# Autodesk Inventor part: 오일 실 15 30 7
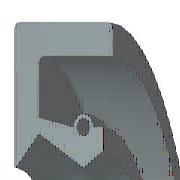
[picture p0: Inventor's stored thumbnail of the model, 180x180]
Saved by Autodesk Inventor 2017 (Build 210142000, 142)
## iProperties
IsCustomPart: 1
Created: 2012-02
Part Number: 오일 실 15 30 7
Material: 고무
Description: 오일-실
Document SubType Name: Modeling
Standard: KS B 2804
Designer: mduedu
Standards Organization: KS
Language: ko-KR
Size Designation: D - 15 30 7
Categories: <MemberInstance><Categories><Category DisplayName="샤프트 부품" InternalName="7f7aeb1f-a693-4053-b835-cee3144e0d98" Mnemonic="SHFT"><Category DisplayName="실링" Intern
Density: 0.93 g/cm^3
Appearance: 고무 - 검은색 - 버전 1.1
Author: mduedu
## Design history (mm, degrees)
revolve "본체" stored, may be unused: angle "d17" = 90 deg
revolve "스프링1" stored, may be unused: angle "d18" = 90 deg
body "Solid1"
sketch "스케치1"
  geometry: L1 (0, 15)-(7, 15); L2 (7, 13.25)-(1.75, 13.25); L3 (1.75, 9.25)-(4.9, 7.5); L4 (4.9, 7.5)-(0, 7.5); L5 (0, 0)-(9.586, 0) reference; L6 (4.9, 7.5)-(6.3, 8.375); L7 (0, 18)-(0, -3) reference; L8 (-1.941, 0)-(11.507, 0) reference; L9 (4.2, 9.6)-(1.75, 10.09); L10 (1.75, 10.09)-(1.75, 13.25); L11 (0, 15)-(0, 7.588); L12 (4.9, 7.5)-(0, 7.5); L13 (1.75, 9.25)-(0.152, 7.528); L14 (7, 15)-(7, 13.25); L15 (5.6, 9.6)-(6.3, 9.6); L16 (6.3, 9.6)-(6.3, 8.375); C1 r 0.455 at (4.9, 9.6); A1 r 0.7 centre (4.9, 9.6) between (5.6, 9.6) and (4.2, 9.6); A2 r 0.088 centre (0.088, 7.588) between (0, 7.588) and (0.152, 7.528); 1 further point
  constraints: 28 end point, 5 horizontal alignment, 5 point on line, 4 point on circle, 4 vertical alignment, 3 centre point, 3 tangent, 2 collinear, 2 horizontal, 2 perpendicular, 1 coincident, 1 parallel
  dimensions: "d0" = 30 diameter of L1 L5 (= SD2); "d1" = 1.75 distance of L1.end L2.start (= SD); "d2" = 0.91 diameter of C1 (= SPDI); "d3" = 1.4 diameter of A1 (= SPDA); "d4" = 15 diameter of L3.end L5 (= NND); "d5" = 18.5 diameter of L3.start L5 (= TKDM); "d7" = 20.18 diameter of L9.end L5 (= TKDM + 0.24 x SWDT); "d8" = 1.75 distance between parallel lines of L11 L10 (= SD); "d9" = 4.9 distance from line of L11 C1.centre (= SPDST); "d10" = 19.2 diameter of C1.centre L5 (= HLDM); "d11" = 0.0875 radius of A2 (= 0.25 x LAB); "d12" = 6.3 distance between parallel lines of L11 L16 (= SDI); "d13" = 16.75 diameter of L6.end L5 (= ABDM); "d14" = 7 distance from line of L11 L1.end (= SWDT)
fillet "모깎기1" dims "d6" = 0.3 (= RR)
other parameters: "SD2" = 30 [user parameter; used in 1 equation term], "SWDT" = 7 [user parameter; used in 2 equation terms], "RR" = 0.3 [user parameter; used in 1 equation term], "SD" = 1.75 [user parameter; used in 2 equation terms], "NND" = 15 [user parameter; used in 1 equation term], "SPDA" = 1.4 [user parameter; used in 1 equation term], "SPDI" = 0.91 [user parameter; used in 1 equation term], "TKDM" = 18.5 [user parameter; used in 2 equation terms], "HLDM" = 19.2 [user parameter; used in 1 equation term], "ABDM" = 16.75 [user parameter; used in 1 equation term], "SDI" = 6.3 [user parameter; used in 1 equation term], "SPDST" = 4.9 [user parameter; used in 1 equation term], "LAB" = 0.35 [user parameter; used in 1 equation term], "d15" = 0, "d16" = 0, "d19" = 0
